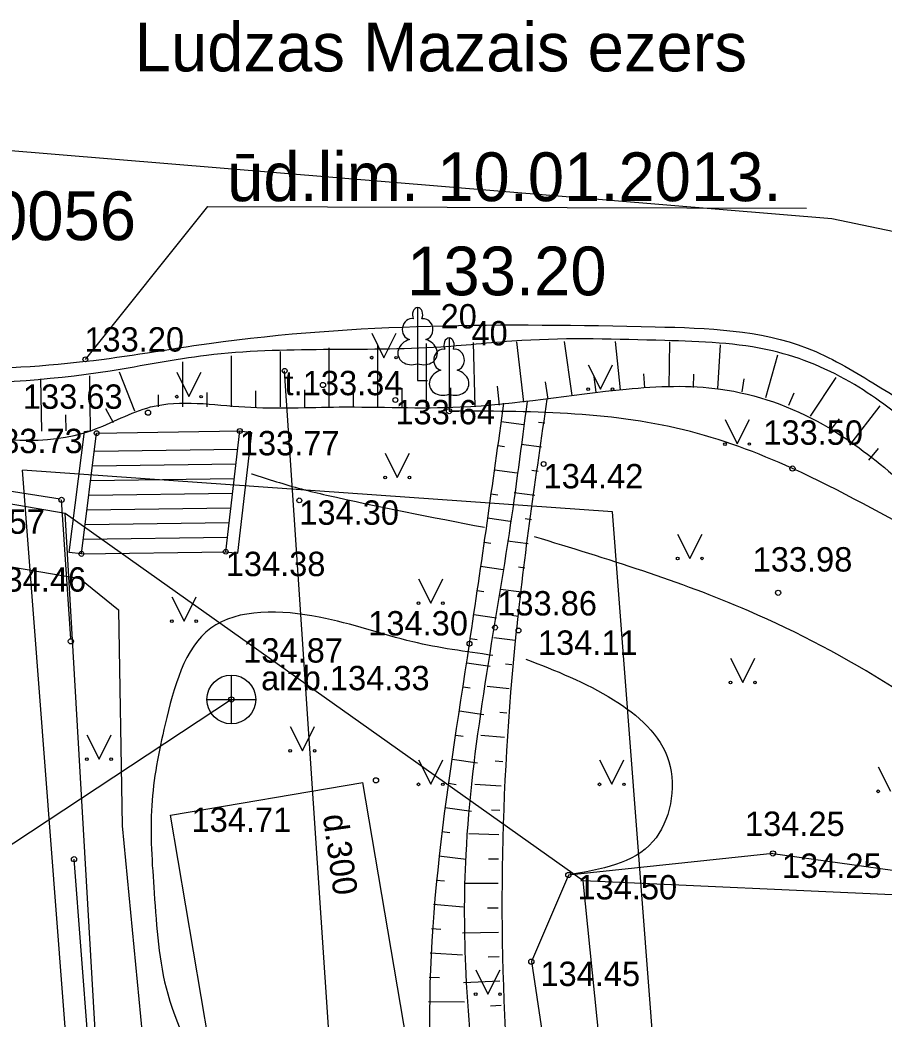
# Model space of a CAD drawing. Extents: x 728710 to 728960, y 272811 to 273475.
# Drawn here: x 728770.77 to 728788.49, y 273405.27 to 273425.76 of the extents above; entities that cross this region are included whole.
import ezdxf

# ---------------------------------------------------------------- set-up
doc = ezdxf.new("R2010")
doc.units = 0
for name, color, linetype in [('HIDG_HNOS_####_TKST_#', 7, 'Continuous'), ('Level 12', 7, 'Continuous'), ('Level 18', 7, 'Continuous'), ('Level 23', 7, 'Continuous'), ('Level 27', 7, 'Continuous'), ('Level 28', 7, 'Continuous'), ('Level 29', 7, 'Continuous'), ('Level 30', 7, 'Continuous'), ('Level 31', 7, 'Continuous'), ('Level 33', 7, 'Continuous'), ('Level 34', 7, 'Continuous'), ('Level 35', 7, 'Continuous'), ('Level 4', 7, 'Continuous'), ('Level 42', 7, 'Continuous'), ('Level 48', 7, 'Continuous'), ('Level 56', 7, 'Continuous'), ('Level 57', 7, 'Continuous'), ('Level 60', 7, 'Continuous'), ('Level 8', 7, 'Continuous'), ('RAMI_PLAN_####_TKST_#', 7, 'Continuous'), ('RAMI_UZMR_####_####_#', 7, 'Continuous'), ('RELJ_NOGA_####_####_#', 7, 'Continuous'), ('ROBZ_ELEM_####_####_#', 7, 'Continuous'), ('ROBZ_IERR_####_####_#', 7, 'Continuous'), ('ROBZ_KADS_####_TKST_#', 7, 'Continuous'), ('ROBZ_UZMR_####_####_#', 7, 'Continuous'), ('TERT_KONT_####_####_#', 7, 'Continuous')]:
    doc.layers.add(name, color=color, linetype=linetype)

msp = doc.modelspace()

# ---------------------------------------------------------------- linework, layer by layer
at = {"layer": 'HIDG_HNOS_####_TKST_#'}
msp.add_lwpolyline([(728772.11, 273418.796), (728774.62, 273421.928), (728786.905, 273421.897)], dxfattribs=at)
at = {"layer": 'Level 12'}
for p, q in [((728779.109, 273417.819), (728779.109, 273419.121)), ((728780.108, 273417.828), (728780.071, 273419.144)), ((728781.104, 273417.916), (728780.962, 273419.156)), ((728782.095, 273418.053), (728781.936, 273419.165)), ((728783.087, 273418.174), (728782.987, 273419.164)), ((728784.085, 273418.225), (728784.097, 273419.153)), ((728776.109, 273417.819), (728776.109, 273418.957)), ((728777.109, 273417.819), (728777.109, 273419.029)), ((728778.109, 273417.819), (728778.109, 273419.08)), ((728785.085, 273418.189), (728785.14, 273419.093)), ((728774.109, 273417.819), (728774.109, 273418.743)), ((728775.109, 273417.819), (728775.109, 273418.866)), ((728786.067, 273418.016), (728786.311, 273418.886)), ((728773.122, 273417.735), (728772.809, 273418.531)), ((728771.216, 273417.324), (728771.199, 273418.395)), ((728772.216, 273417.34), (728772.198, 273418.461)), ((728781.6, 273417.981), (728781.549, 273418.336)), ((728782.59, 273418.12), (728782.549, 273418.434)), ((728783.586, 273418.21), (728783.568, 273418.496)), ((728784.585, 273418.219), (728784.589, 273418.495)), ((728785.581, 273418.128), (728785.624, 273418.393)), ((728786.986, 273417.63), (728787.514, 273418.426)), ((728774.609, 273417.819), (728774.609, 273418.117)), ((728775.609, 273417.819), (728775.609, 273418.148)), ((728776.609, 273417.819), (728776.609, 273418.172)), ((728777.609, 273417.819), (728777.609, 273418.191)), ((728778.609, 273417.819), (728778.609, 273418.203)), ((728779.609, 273417.819), (728779.609, 273418.213)), ((728780.607, 273417.859), (728780.563, 273418.247)), ((728786.54, 273417.855), (728786.652, 273418.109)), ((728773.609, 273417.819), (728773.609, 273418.071)), ((728781.6, 273417.983), (728781.599, 273417.983)), ((728772.686, 273417.491), (728772.532, 273417.781)), ((728787.791, 273417.038), (728788.411, 273417.843)), ((728771.716, 273417.332), (728771.711, 273417.661)), ((728780.642, 273417.523), (728781.105, 273417.457)), ((728781.532, 273417.487), (728781.408, 273417.504)), ((728787.395, 273417.343), (728787.576, 273417.578)), ((728780.571, 273417.028), (728780.71, 273417.008)), ((728781.464, 273416.992), (728781.047, 273417.049)), ((728788.182, 273416.726), (728788.38, 273416.968)), ((728780.5, 273416.533), (728780.964, 273416.467)), ((728781.397, 273416.496), (728781.271, 273416.514)), ((728780.429, 273416.038), (728780.569, 273416.018)), ((728781.329, 273416.001), (728780.906, 273416.059)), ((728780.358, 273415.543), (728780.824, 273415.477)), ((728781.262, 273415.506), (728781.134, 273415.523)), ((728780.287, 273415.048), (728780.427, 273415.028)), ((728781.194, 273415.01), (728780.766, 273415.069)), ((728780.217, 273414.553), (728780.683, 273414.487)), ((728781.127, 273414.515), (728780.997, 273414.532)), ((728780.146, 273414.058), (728780.286, 273414.038)), ((728781.059, 273414.019), (728780.626, 273414.078)), ((728780.075, 273413.564), (728780.545, 273413.496)), ((728780.991, 273413.524), (728780.861, 273413.542)), ((728780.004, 273413.069), (728780.146, 273413.048)), ((728780.924, 273413.028), (728780.49, 273413.087)), ((728779.932, 273412.574), (728780.411, 273412.502)), ((728780.861, 273412.532), (728780.729, 273412.548)), ((728779.858, 273412.079), (728780.004, 273412.057)), ((728780.804, 273412.036), (728780.355, 273412.084)), ((728779.782, 273411.585), (728780.28, 273411.509)), ((728780.754, 273411.538), (728780.615, 273411.552)), ((728779.707, 273411.091), (728779.859, 273411.068)), ((728780.709, 273411.04), (728780.224, 273411.08)), ((728779.631, 273410.597), (728780.153, 273410.518)), ((728780.671, 273410.542), (728780.518, 273410.553)), ((728779.558, 273410.102), (728779.718, 273410.078)), ((728780.639, 273410.043), (728780.097, 273410.075)), ((728779.487, 273409.607), (728780.03, 273409.531)), ((728780.613, 273409.543), (728780.44, 273409.551)), ((728779.421, 273409.111), (728779.586, 273409.09)), ((728780.594, 273409.044), (728779.973, 273409.063)), ((728779.359, 273408.615), (728779.919, 273408.549)), ((728780.581, 273408.544), (728780.382, 273408.548)), ((728779.303, 273408.118), (728779.476, 273408.1)), ((728780.574, 273408.044), (728779.881, 273408.048)), ((728779.254, 273407.621), (728779.857, 273407.568)), ((728780.574, 273407.544), (728780.359, 273407.542)), ((728779.213, 273407.122), (728779.403, 273407.108)), ((728780.581, 273407.044), (728779.846, 273407.03)), ((728779.182, 273406.623), (728779.849, 273406.587)), ((728780.595, 273406.544), (728780.371, 273406.536)), ((728779.161, 273406.124), (728779.371, 273406.117)), ((728780.615, 273406.045), (728779.867, 273406.01)), ((728779.151, 273405.624), (728779.889, 273405.621)), ((728780.642, 273405.545), (728780.419, 273405.532))]:
    msp.add_line(p, q, dxfattribs=at)
for points in [[(728769.216, 273417.292), (728772.241, 273417.34), (728773.448, 273417.819), (728775.383, 273417.819), (728777.318, 273417.819), (728779.801, 273417.819), (728783.205, 273418.186), (728785.14, 273418.186), (728787.244, 273417.459), (728789.982, 273415.263), (728791.949, 273413.779), (728793.31, 273413.264), (728794.399, 273413.446), (728797.122, 273414.264), (728798.559, 273414.445), (728799.618, 273414.188), (728800.193, 273413.567), (728800.36, 273412.37), (728800.012, 273411.25), (728798.652, 273409.873), (728798.03, 273409.023), (728797.606, 273407.887), (728797.007, 273406.767)], [(728781.578, 273417.978), (728780.943, 273413.169), (728780.822, 273403.542), (728781.949, 273395.724), (728783.589, 273385.96), (728783.878, 273383.473), (728783.979, 273382.874), (728783.979, 273382.553), (728783.717, 273382.35), (728783.447, 273382.528), (728783.355, 273382.891), (728782.193, 273386.189), (728780.645, 273395.989), (728779.246, 273403.69), (728779.989, 273412.965), (728780.695, 273417.894)]]:
    msp.add_spline(points, degree=3, dxfattribs=at)
at = {"layer": 'Level 18'}
msp.add_lwpolyline([(728779.523, 273368.911), (728776.197, 273418.56)], dxfattribs=at)
at = {"layer": 'Level 23'}
msp.add_lwpolyline([(728775.104, 273411.821), (728750.664, 273395.692)], dxfattribs=at)
at = {"layer": 'Level 27'}
msp.add_line((728786.214, 273408.662), (728782.018, 273408.22), dxfattribs=at)
at = {"layer": 'Level 28'}
for p, q in [((728786.214, 273408.662), (728794.012, 273407.568)), ((728782.018, 273408.22), (728781.258, 273406.444))]:
    msp.add_line(p, q, dxfattribs=at)
msp.add_lwpolyline([(728781.258, 273406.444), (728784.764, 273383.035), (728785.687, 273382.659)], dxfattribs=at)
at = {"layer": 'Level 29'}
for p, q in [((728775.104, 273411.321), (728775.104, 273412.321)), ((728774.604, 273411.821), (728775.604, 273411.821))]:
    msp.add_line(p, q, dxfattribs=at)
msp.add_circle((728775.104, 273411.821), 0.5, dxfattribs=at)
at = {"layer": 'Level 30'}
for points in [[(728792.745, 273413.452), (728789.478, 273415.073), (728786.615, 273416.557), (728784.378, 273417.35), (728779.57, 273417.734)], [(728780.467, 273412.725), (728778.825, 273413.003), (728776.905, 273413.509), (728774.681, 273413.282), (728773.747, 273411.312), (728773.47, 273409.648), (728773.521, 273407.852), (728773.798, 273405.783), (728774.861, 273403.52)], [(728781.143, 273412.65), (728782.942, 273411.815), (728784.079, 273410.551), (728783.751, 273408.906), (728782.018, 273408.22)]]:
    msp.add_spline(points, degree=3, dxfattribs=at)
at = {"layer": 'Level 31'}
for points in [[(728775.514, 273416.448), (728775.523, 273416.445), (728776.031, 273416.287), (728776.542, 273416.137), (728777.059, 273416.012), (728780.295, 273415.352)], [(728794.012, 273407.568), (728791.349, 273410.099), (728785.715, 273413.636), (728781.324, 273415.156)]]:
    msp.add_spline(points, degree=3, dxfattribs=at)
at = {"layer": 'Level 33'}
msp.add_spline([(728769.065, 273418.557), (728772.12, 273418.756), (728774.651, 273419.122), (728783.799, 273419.463), (728786.916, 273419.027), (728788.265, 273418.314), (728790.708, 273416.501), (728792.526, 273414.874), (728793.589, 273414.671), (728795.387, 273414.917), (728797.984, 273415.774), (728799.237, 273415.773), (728800.894, 273414.901), (728801.653, 273413.507), (728801.685, 273412.251), (728801.253, 273410.766), (728799.842, 273408.86), (728798.822, 273407.273), (728798.368, 273406.856), (728798.53, 273406.513)], degree=3, dxfattribs=at)
at = {"layer": 'Level 34'}
for points in [[(728803.711, 273405.484), (728801.422, 273405.484), (728800.253, 273405.69), (728798.991, 273406.049), (728798.257, 273406.395), (728798.035, 273406.78), (728799.137, 273408.348), (728800.771, 273410.635), (728801.169, 273411.645), (728801.395, 273412.814), (728801.395, 273413.639), (728800.811, 273414.542), (728800.187, 273415.101), (728799.098, 273415.433), (728798.208, 273415.433), (728796.959, 273415.154), (728795.698, 273414.702), (728794.542, 273414.463), (728793.32, 273414.463), (728792.63, 273414.463), (728791.78, 273415.127), (728789.217, 273417.32), (728787.889, 273418.277), (728786.202, 273418.969), (728783.997, 273419.181), (728781.062, 273419.181), (728779.402, 273419.048), (728774.594, 273418.875), (728772.615, 273418.556), (728768.674, 273418.296), (728764.235, 273418.663), (728759.321, 273419.221), (728753.876, 273419.779), (728749.613, 273420.085), (728745.469, 273420.085), (728743.998, 273420.191)], [(728781.172, 273417.937), (728780.8, 273415.225), (728779.913, 273408.639), (728779.913, 273406.196), (728780.192, 273403.172), (728781.656, 273394.054), (728782.888, 273385.843), (728783.581, 273383.144)]]:
    msp.add_spline(points, degree=3, dxfattribs=at)
at = {"layer": 'Level 35'}
msp.add_lwpolyline([(728744.077, 273418.442), (728754.56, 273418.606), (728771.59, 273415.937)], dxfattribs=at)
at = {"layer": 'Level 4'}
for p, q in [((728773.859, 273409.451), (728777.803, 273410.117)), ((728781.219, 273389.895), (728777.803, 273410.117)), ((728777.326, 273388.924), (728773.859, 273409.451))]:
    msp.add_line(p, q, dxfattribs=at)
at = {"layer": 'Level 42'}
msp.add_lwpolyline([(728744.127, 273417.336), (728753.529, 273417.32), (728763.941, 273415.674), (728771.995, 273414.301), (728772.789, 273413.658), (728772.866, 273409.228), (728774.333, 273393.944), (728774.498, 273390.902), (728774.316, 273388.778), (728772.706, 273388.348), (728772.062, 273387.726), (728772.188, 273385.974), (728773.233, 273385.001), (728774.349, 273385.73), (728774.847, 273385.541), (728775.23, 273379.296), (728776.795, 273371.75), (728778.361, 273363.303)], dxfattribs=at)
at = {"layer": 'Level 48'}
for centre, radius in [((728772.11, 273418.796), 0.05), ((728776.197, 273418.56), 0.05), ((728776.983, 273418.27), 0.0534), ((728778.469, 273417.963), 0.05), ((728773.395, 273417.703), 0.0534), ((728779.57, 273417.734), 0.0534), ((728772.341, 273417.283), 0.05), ((728775.278, 273417.327), 0.05), ((728781.509, 273416.65), 0.05), ((728786.615, 273416.557), 0.0534), ((728771.621, 273415.913), 0.0534), ((728776.498, 273415.903), 0.05), ((728772.028, 273414.806), 0.05), ((728774.989, 273414.85), 0.05), ((728786.32, 273414.008), 0.0534), ((728780.514, 273413.295), 0.05), ((728780.995, 273413.236), 0.05), ((728771.813, 273413.013), 0.0534), ((728779.989, 273412.965), 0.05), ((728775.104, 273411.821), 0.0534), ((728778.071, 273410.162), 0.0534), ((728786.214, 273408.662), 0.0534), ((728771.877, 273408.545), 0.0534), ((728782.018, 273408.22), 0.0534), ((728781.258, 273406.444), 0.0534)]:
    msp.add_circle(centre, radius, dxfattribs=at)
at = {"layer": 'Level 8'}
for p, q in [((728771.813, 273413.067), (728771.621, 273415.913)), ((728772.98, 273394.153), (728771.877, 273408.545))]:
    msp.add_line(p, q, dxfattribs=at)
at = {"layer": 'RAMI_UZMR_####_####_#'}
msp.add_lwpolyline([(728810.773, 273260.978), (728802.611, 273315.901), (728795.796, 273348.362), (728794.274, 273357.438), (728805.771, 273362.009), (728805.234, 273373.998), (728803.936, 273379.727), (728791.234, 273379.578), (728787.734, 273403.429), (728803.558, 273404.599), (728803.908, 273418.239), (728787.419, 273421.679), (728754.475, 273424.404), (728743.982, 273420.563), (728745.23, 273392.888), (728745.879, 273378.489), (728747.149, 273361.103), (728773.116, 273356.557), (728775.22, 273317.659), (728767.872, 273315.668), (728768.286, 273308.258), (728775.846, 273306.093), (728776.746, 273299.712), (728774.767, 273288.109)], dxfattribs=at)
at = {"layer": 'ROBZ_ELEM_####_####_#'}
msp.add_line((728782.92, 273415.669), (728770.82, 273416.523), dxfattribs=at)
for points in [[(728775.108, 273376.265), (728772.453, 273395.191), (728770.82, 273416.523)], [(728787.679, 273373.026), (728784.39, 273396.483), (728782.92, 273415.669)]]:
    msp.add_lwpolyline(points, dxfattribs=at)
at = {"layer": 'ROBZ_IERR_####_####_#'}
for p, q in [((728771.78, 273414.837), (728772.093, 273417.315)), ((728772.028, 273414.806), (728772.341, 273417.283)), ((728772.093, 273417.315), (728772.241, 273417.34)), ((728775.237, 273414.821), (728775.526, 273417.298)), ((728775.278, 273417.327), (728775.526, 273417.298)), ((728772.294, 273416.91), (728775.234, 273416.954)), ((728772.256, 273416.61), (728775.199, 273416.653)), ((728772.218, 273416.309), (728775.164, 273416.353)), ((728772.18, 273416.008), (728775.129, 273416.052)), ((728772.142, 273415.708), (728775.094, 273415.752)), ((728772.104, 273415.407), (728775.059, 273415.451)), ((728772.066, 273415.107), (728775.024, 273415.151)), ((728772.028, 273414.806), (728771.78, 273414.837)), ((728774.989, 273414.85), (728775.237, 273414.821))]:
    msp.add_line(p, q, dxfattribs=at)
for points in [[(728772.341, 273417.283), (728775.278, 273417.327)], [(728774.989, 273414.85), (728775.278, 273417.327)], [(728772.028, 273414.806), (728774.989, 273414.85)]]:
    msp.add_lwpolyline(points, dxfattribs=at)
at = {"layer": 'ROBZ_UZMR_####_####_#'}
for p, q in [((728771.692, 273415.636), (728754.544, 273418.603)), ((728772.942, 273394.12), (728771.692, 273415.636)), ((728782.32, 273408.103), (728771.692, 273415.636)), ((728784.885, 273382.939), (728782.32, 273408.103)), ((728794.012, 273407.568), (728782.32, 273408.103))]:
    msp.add_line(p, q, dxfattribs=at)
at = {"layer": 'TERT_KONT_####_####_#'}
for p, q in [((728777.984, 273419.33), (728778.234, 273418.83)), ((728778.234, 273418.83), (728778.484, 273419.33)), ((728778.926, 273418.707), (728778.926, 273418.36)), ((728773.984, 273418.531), (728774.234, 273418.031)), ((728774.234, 273418.031), (728774.484, 273418.531)), ((728782.424, 273418.684), (728782.674, 273418.184)), ((728782.674, 273418.184), (728782.924, 273418.684)), ((728778.926, 273418.36), (728779.126, 273418.36)), ((728779.57, 273418.081), (728779.57, 273417.734)), ((728779.57, 273417.734), (728779.77, 273417.734)), ((728785.231, 273417.56), (728785.481, 273417.06)), ((728785.481, 273417.06), (728785.731, 273417.56)), ((728778.257, 273416.873), (728778.507, 273416.373)), ((728778.507, 273416.373), (728778.757, 273416.873)), ((728784.259, 273415.214), (728784.509, 273414.714)), ((728784.509, 273414.714), (728784.759, 273415.214)), ((728778.943, 273414.296), (728779.193, 273413.796)), ((728779.193, 273413.796), (728779.443, 273414.296)), ((728773.884, 273413.927), (728774.134, 273413.427)), ((728774.134, 273413.427), (728774.384, 273413.927)), ((728785.345, 273412.669), (728785.595, 273412.169)), ((728785.595, 273412.169), (728785.845, 273412.669)), ((728776.313, 273411.267), (728776.563, 273410.767)), ((728776.563, 273410.767), (728776.813, 273411.267)), ((728772.141, 273411.095), (728772.391, 273410.595)), ((728772.391, 273410.595), (728772.641, 273411.095)), ((728778.943, 273410.581), (728779.193, 273410.081)), ((728779.193, 273410.081), (728779.443, 273410.581)), ((728782.658, 273410.581), (728782.908, 273410.081)), ((728782.908, 273410.081), (728783.158, 273410.581)), ((728788.375, 273410.438), (728788.625, 273409.938)), ((728780.116, 273406.278), (728780.366, 273405.778)), ((728780.366, 273405.778), (728780.616, 273406.278))]:
    msp.add_line(p, q, dxfattribs=at)
for points in [[(728778.926, 273419.86), (728778.926, 273418.707)], [(728779.015, 273419.628), (728779.014, 273419.629)], [(728779.57, 273419.234), (728779.57, 273418.081)], [(728779.66, 273419.002), (728779.659, 273419.003)]]:
    msp.add_lwpolyline(points, dxfattribs=at)
for centre, radius in [((728777.983, 273418.83), 0.028), ((728778.483, 273418.83), 0.0263), ((728782.424, 273418.183), 0.028), ((728782.924, 273418.183), 0.0263), ((728773.983, 273418.031), 0.028), ((728774.483, 273418.031), 0.0263), ((728785.23, 273417.059), 0.028), ((728785.73, 273417.059), 0.0263), ((728778.257, 273416.373), 0.028), ((728778.757, 273416.373), 0.0263), ((728784.259, 273414.714), 0.028), ((728784.759, 273414.714), 0.0263), ((728778.943, 273413.796), 0.028), ((728779.443, 273413.796), 0.0263), ((728773.884, 273413.427), 0.028), ((728774.384, 273413.427), 0.0263), ((728785.345, 273412.168), 0.028), ((728785.845, 273412.168), 0.0263), ((728776.313, 273410.767), 0.028), ((728776.813, 273410.767), 0.0263), ((728772.14, 273410.595), 0.028), ((728772.64, 273410.595), 0.0263), ((728778.943, 273410.08), 0.028), ((728779.443, 273410.08), 0.0263), ((728782.658, 273410.08), 0.028), ((728783.158, 273410.08), 0.0263), ((728788.374, 273409.937), 0.028), ((728780.116, 273405.777), 0.028), ((728780.616, 273405.777), 0.0263)]:
    msp.add_circle(centre, radius, dxfattribs=at)
for centre, major_axis, ratio, start_param, end_param in [((728778.926, 273419.71), (0, -0.15), 0.707107, 3.14537, 5.287485), ((728778.925, 273419.71), (0, -0.15), 0.707107, 0.995701, 3.137816), ((728778.798, 273419.416), (-0.039, -0.212), 0.861323, 3.141593, 6.283185), ((728779.054, 273419.416), (0.039, -0.212), 0.861323, 0, 3.141593), ((728778.836, 273418.953), (0.307, 0.095), 0.814445, 1.570796, 4.752015), ((728779.015, 273418.953), (-0.307, 0.095), 0.814445, 1.531171, 4.712389), ((728779.57, 273419.084), (0, -0.15), 0.707107, 3.14537, 5.287485), ((728779.57, 273419.084), (0, -0.15), 0.707107, 0.995701, 3.137816), ((728779.442, 273418.789), (-0.039, -0.212), 0.861323, 3.141593, 6.283185), ((728779.698, 273418.789), (0.039, -0.212), 0.861323, 0, 3.141593), ((728779.48, 273418.327), (0.307, 0.095), 0.814445, 1.570796, 4.752015), ((728779.66, 273418.327), (-0.307, 0.095), 0.814445, 1.531171, 4.712389)]:
    msp.add_ellipse(centre, major_axis=major_axis, ratio=ratio, start_param=start_param, end_param=end_param, dxfattribs=at)

# ---------------------------------------------------------------- texts
at = {"layer": 'HIDG_HNOS_####_TKST_#'}
for s, p in [('Ludzas Mazais ezers', (728773.122, 273424.702)), ('ūd.lim. 10.01.2013.', (728775.017, 273422.04)), ('133.20', (728778.711, 273420.109))]:
    msp.add_text(s, height=1, dxfattribs=at).set_placement(p)
at = {"layer": 'Level 56'}
msp.add_text(' 134.87', height=0.5, dxfattribs=at).set_placement((728775.162, 273412.577))
at = {"layer": 'Level 57'}
for s, p in [('133.20', (728772.089, 273418.955)), (' 133.63', (728770.643, 273417.781)), ('133.64', (728778.469, 273417.463)), (' 133.50', (728785.831, 273417.044)), ('133.73', (728770.011, 273416.872)), ('133.77', (728775.278, 273416.827)), ('134.42', (728781.509, 273416.15)), ('134.30', (728776.498, 273415.403)), ('134.57', (728769.234, 273415.218)), ('134.38', (728774.989, 273414.35)), (' 133.98', (728785.612, 273414.444)), ('134.46', (728770.079, 273414.032)), ('133.86', (728780.559, 273413.543)), ('134.30', (728777.912, 273413.133)), ('134.11', (728781.394, 273412.736)), (' 134.71', (728774.101, 273409.105)), (' 134.25', (728785.455, 273409.022)), (' 134.25', (728786.214, 273408.162)), (' 134.50', (728782.018, 273407.72)), (' 134.45', (728781.258, 273405.944))]:
    msp.add_text(s, height=0.5, dxfattribs=at).set_placement(p)
at = {"layer": 'Level 60'}
msp.add_text('aizb.134.33', height=0.5, dxfattribs=at).set_placement((728775.714, 273412.01))
at = {"layer": 'RAMI_PLAN_####_TKST_#'}
msp.add_text('t.133.34', height=0.5, dxfattribs=at).set_placement((728776.197, 273418.06))
msp.add_text('d.300', height=0.5, rotation=277.7894, dxfattribs=at).set_placement((728776.979, 273409.439))
at = {"layer": 'RELJ_NOGA_####_####_#'}
for s, p in [('20', (728779.396, 273419.429)), ('40', (728780.029, 273419.082))]:
    msp.add_text(s, height=0.5, dxfattribs=at).set_placement(p)
at = {"layer": 'ROBZ_KADS_####_TKST_#'}
msp.add_text('68010040056', height=1, dxfattribs=at).set_placement((728764.968, 273421.24))

doc.saveas('drawing.dxf')
